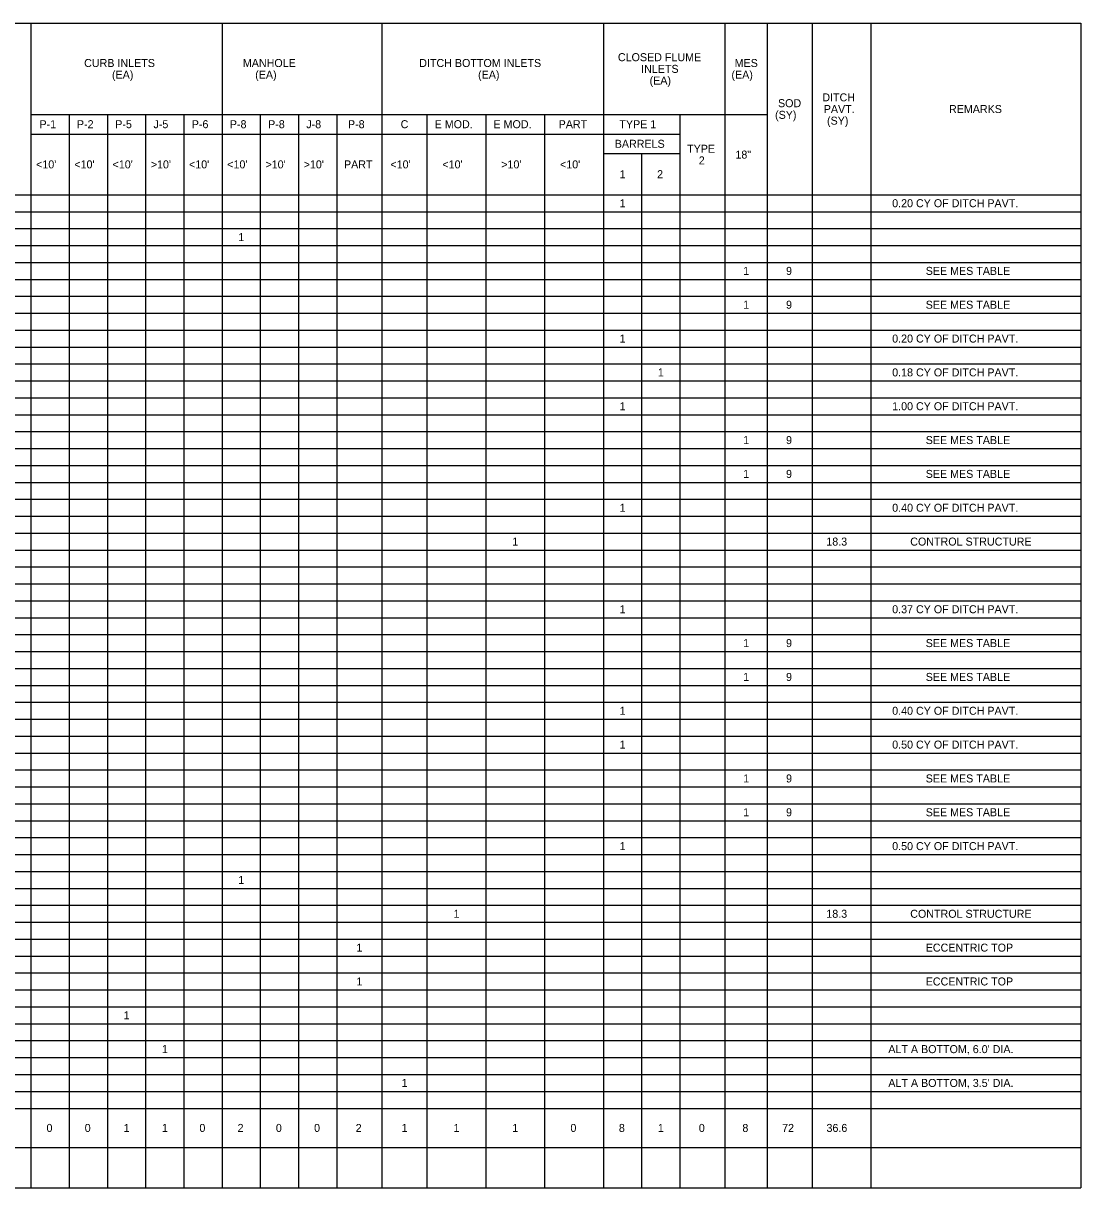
# Model space of a CAD drawing. Extents: x 0 to 765, y -1227 to 479.
# Drawn here: x 360 to 764.5, y -569 to -123.3 of the extents above; entities that cross this region are included whole.
import ezdxf

# ---------------------------------------------------------------- set-up
doc = ezdxf.new("R2010")
doc.units = 0
for name, color, linetype in [('Miscellaneous0', 7, 'Continuous'), ('PlotBorder_dp', 7, 'Continuous'), ('SheetLines_dp', 7, 'Continuous'), ('TextMinor', 7, 'Continuous')]:
    doc.layers.add(name, color=color, linetype=linetype)

msp = doc.modelspace()

# ---------------------------------------------------------------- linework, layer by layer
at = {"layer": 'PlotBorder_dp'}
for p, q in [((362.91, -123.31), (362.91, -188.93)), ((362.91, -123.31), (362.91, -568.96)), ((436.04, -123.31), (436.04, -158.18)), ((497.16, -123.31), (497.16, -568.96)), ((497.16, -123.31), (497.16, -568.96)), ((581.91, -123.31), (581.91, -568.96)), ((581.91, -123.31), (581.91, -568.96)), ((628.41, -123.31), (628.41, -568.96)), ((628.41, -123.31), (628.41, -568.96)), ((644.54, -123.31), (644.54, -568.96)), ((644.54, -123.31), (644.54, -568.96)), ((661.79, -123.31), (661.79, -568.96)), ((661.79, -123.31), (661.79, -568.96)), ((684.29, -123.31), (684.29, -188.93)), ((684.29, -123.31), (684.29, -568.96)), ((362.91, -158.18), (644.54, -158.18)), ((362.91, -158.18), (644.54, -158.18)), ((377.54, -158.18), (377.54, -188.93)), ((377.54, -158.18), (377.54, -568.96)), ((392.16, -158.18), (392.16, -188.93)), ((392.16, -158.18), (392.16, -568.96)), ((406.79, -158.18), (406.79, -568.96)), ((421.41, -158.18), (421.41, -553.58)), ((421.41, -158.18), (421.41, -568.96)), ((436.04, -158.18), (436.04, -568.96)), ((450.66, -158.18), (450.66, -568.96)), ((450.66, -158.18), (450.66, -568.96)), ((465.29, -158.18), (465.29, -568.96)), ((465.29, -158.18), (465.29, -568.96)), ((479.91, -158.18), (479.91, -568.96)), ((479.91, -158.18), (479.91, -568.96)), ((514.41, -158.18), (514.41, -568.96)), ((514.41, -158.18), (514.41, -568.96)), ((536.91, -158.18), (536.91, -568.96)), ((536.91, -158.18), (536.91, -568.96)), ((559.41, -158.18), (559.41, -568.96)), ((559.41, -158.18), (559.41, -568.96)), ((611.16, -158.18), (611.16, -568.96)), ((611.16, -158.18), (611.16, -568.96)), ((362.91, -165.68), (559.41, -165.68)), ((362.91, -165.68), (611.16, -165.68)), ((406.79, -165.68), (406.79, -553.58)), ((436.04, -165.68), (436.04, -568.96)), ((581.91, -165.68), (611.16, -165.68)), ((581.91, -173.18), (611.16, -173.18)), ((581.91, -173.18), (611.16, -173.18)), ((596.54, -173.18), (596.54, -568.96)), ((596.54, -173.18), (596.54, -568.96)), ((362.91, -422.03), (362.91, -568.96)), ((377.54, -422.03), (377.54, -553.58)), ((392.16, -422.03), (392.16, -553.58)), ((0.29, -538.58), (764.54, -538.58)), ((684.29, -538.58), (684.29, -568.96)), ((85.04, -553.58), (764.54, -553.58)), ((85.04, -553.58), (764.54, -553.58))]:
    msp.add_line(p, q, dxfattribs=at)
at = {"layer": 'SheetLines_dp'}
for p, q in [((0.29, -123.31), (764.54, -123.31)), ((764.54, -123.31), (764.54, -568.96)), ((0.29, -188.93), (764.54, -188.93)), ((40.04, -188.93), (764.54, -188.93)), ((0.29, -568.96), (764.54, -568.96))]:
    msp.add_line(p, q, dxfattribs=at)
at = {"layer": 'TextMinor'}
for p, q in [((0.29, -195.41), (764.54, -195.41)), ((173.54, -195.41), (406.79, -195.41)), ((421.41, -195.41), (764.54, -195.41)), ((0.29, -201.88), (764.54, -201.88)), ((0.29, -201.88), (764.54, -201.88)), ((0.29, -208.36), (764.54, -208.36)), ((0.29, -208.36), (764.54, -208.36)), ((0.29, -214.83), (764.54, -214.83)), ((0.29, -214.83), (764.54, -214.83)), ((0.29, -221.31), (764.54, -221.31)), ((0.29, -221.31), (764.54, -221.31)), ((0.29, -227.78), (764.54, -227.78)), ((0.29, -227.78), (764.54, -227.78)), ((0.29, -234.26), (764.54, -234.26)), ((0.29, -234.26), (764.54, -234.26)), ((0.29, -240.73), (764.54, -240.73)), ((0.29, -240.73), (764.54, -240.73)), ((0.29, -247.21), (764.54, -247.21)), ((0.29, -247.21), (764.54, -247.21)), ((0.29, -253.68), (764.54, -253.68)), ((0.29, -253.68), (764.54, -253.68)), ((0.29, -260.16), (764.54, -260.16)), ((0.29, -260.16), (764.54, -260.16)), ((0.29, -266.63), (764.54, -266.63)), ((0.29, -266.63), (764.54, -266.63)), ((0.29, -273.11), (764.54, -273.11)), ((0.29, -273.11), (764.54, -273.11)), ((0.29, -279.58), (764.54, -279.58)), ((0.29, -279.58), (764.54, -279.58)), ((0.29, -286.06), (764.54, -286.06)), ((0.29, -286.06), (764.54, -286.06)), ((0.29, -292.53), (764.54, -292.53)), ((0.29, -292.53), (764.54, -292.53)), ((0.29, -299.01), (764.54, -299.01)), ((0.29, -299.01), (764.54, -299.01)), ((0.29, -305.48), (764.54, -305.48)), ((0.29, -305.48), (764.54, -305.48)), ((0.29, -311.96), (764.54, -311.96)), ((0.29, -311.96), (764.54, -311.96)), ((0.29, -318.43), (764.54, -318.43)), ((0.29, -318.43), (764.54, -318.43)), ((0.29, -324.91), (764.54, -324.91)), ((0.29, -324.91), (764.54, -324.91)), ((0.29, -331.38), (764.54, -331.38)), ((0.29, -331.38), (764.54, -331.38)), ((0.29, -337.86), (764.54, -337.86)), ((0.29, -337.86), (764.54, -337.86)), ((0.29, -344.33), (764.54, -344.33)), ((0.29, -344.33), (764.54, -344.33)), ((0.29, -350.81), (764.54, -350.81)), ((0.29, -350.81), (764.54, -350.81)), ((0.29, -357.28), (764.54, -357.28)), ((0.29, -357.28), (764.54, -357.28)), ((0.29, -363.76), (764.54, -363.76)), ((0.29, -363.76), (764.54, -363.76)), ((0.29, -370.23), (764.54, -370.23)), ((0.29, -370.23), (764.54, -370.23)), ((0.29, -376.71), (764.54, -376.71)), ((0.29, -376.71), (764.54, -376.71)), ((0.29, -383.18), (764.54, -383.18)), ((0.29, -383.18), (764.54, -383.18)), ((0.29, -389.66), (764.54, -389.66)), ((0.29, -389.66), (764.54, -389.66)), ((0.29, -396.13), (764.54, -396.13)), ((0.29, -396.13), (764.54, -396.13)), ((0.29, -402.61), (764.54, -402.61)), ((0.29, -402.61), (764.54, -402.61)), ((0.29, -409.08), (764.54, -409.08)), ((0.29, -409.08), (764.54, -409.08)), ((0.29, -415.56), (764.54, -415.56)), ((0.29, -415.56), (764.54, -415.56)), ((0.29, -422.03), (764.54, -422.03)), ((0.29, -422.03), (764.54, -422.03)), ((0.29, -428.51), (764.54, -428.51)), ((0.29, -428.51), (764.54, -428.51)), ((0.29, -434.98), (764.54, -434.98)), ((0.29, -434.98), (764.54, -434.98)), ((0.29, -441.46), (764.54, -441.46)), ((0.29, -441.46), (764.54, -441.46)), ((0.29, -447.93), (764.54, -447.93)), ((0.29, -447.93), (764.54, -447.93)), ((0.29, -454.41), (764.54, -454.41)), ((0.29, -454.41), (764.54, -454.41)), ((0.29, -460.88), (764.54, -460.88)), ((0.29, -460.88), (764.54, -460.88)), ((0.29, -467.36), (764.54, -467.36)), ((0.29, -467.36), (764.54, -467.36)), ((0.29, -473.83), (764.54, -473.83)), ((0.29, -473.83), (764.54, -473.83)), ((0.29, -480.31), (764.54, -480.31)), ((0.29, -480.31), (764.54, -480.31)), ((0.29, -486.78), (764.54, -486.78)), ((0.29, -486.78), (764.54, -486.78)), ((0.29, -493.26), (764.54, -493.26)), ((0.29, -493.26), (764.54, -493.26)), ((0.29, -499.73), (764.54, -499.73)), ((0.29, -499.73), (764.54, -499.73)), ((0.29, -506.21), (764.54, -506.21)), ((0.29, -506.21), (764.54, -506.21)), ((0.29, -512.68), (764.54, -512.68)), ((0.29, -512.68), (764.54, -512.68)), ((0.29, -519.16), (764.54, -519.16)), ((0.29, -519.16), (764.54, -519.16)), ((0.29, -525.63), (764.54, -525.63)), ((0.29, -525.63), (764.54, -525.63)), ((0.29, -532.11), (764.54, -532.11)), ((0.29, -532.11), (764.54, -532.11)), ((0.29, -538.58), (764.54, -538.58))]:
    msp.add_line(p, q, dxfattribs=at)

# ---------------------------------------------------------------- texts
at = {"layer": 'Miscellaneous0'}
for s, height, p in [('CURB INLETS', 3.0625, (383.28, -140.04)), ('MANHOLE ', 3.062, (444, -140.04)), ('DITCH BOTTOM INLETS', 3.0625, (511.48, -140.04)), ('CLOSED FLUME', 3.0625, (587.48, -137.81)), ('MES', 3.062, (632.14, -140.04)), ('(EA)', 3.062, (393.93, -144.51)), ('(EA)', 3.062, (448.72, -144.51)), ('(EA)', 3.062, (533.99, -144.51)), ('INLETS', 3.062, (596.38, -142.28)), ('(EA)', 3.062, (630.93, -144.51)), ('(EA)', 3.062, (599.61, -146.74)), ('DITCH', 3.062, (665.69, -153.19)), ('SOD', 3.062, (648.73, -155.42)), ('PAVT.', 3.062, (666.24, -157.65)), ('REMARKS', 3.062, (714.15, -157.65)), ('P-1', 3.062, (366.18, -163.46)), ('P-2', 3.062, (380.51, -163.46)), ('P-5', 3.062, (395.18, -163.46)), ('J-5', 3.062, (409.8, -163.46)), ('P-6', 3.062, (424.45, -163.46)), ('P-8', 3.062, (439.02, -163.46)), ('P-8', 3.062, (453.65, -163.46)), ('J-8', 3.062, (468.27, -163.46)), ('P-8', 3.062, (484.21, -163.46)), ('C', 3.06, (504.35, -163.46)), ('E MOD.', 3.062, (517.38, -163.46)), ('E MOD.', 3.062, (539.88, -163.46)), ('PART', 3.062, (564.81, -163.46)), ('TYPE 1', 3.062, (588.05, -163.46)), ('(SY)', 3.062, (647.61, -159.88)), ('(SY)', 3.062, (667.49, -162.11)), ('BARRELS', 3.062, (586.27, -170.96)), ('TYPE', 3.062, (613.96, -172.86)), ('18"', 3.062, (632.44, -175.09)), ("<10'", 3.062, (364.9, -178.84)), ("<10'", 3.062, (379.52, -178.84)), ("<10'", 3.062, (394.15, -178.84)), (">10'", 3.062, (408.77, -178.84)), ("<10'", 3.062, (423.4, -178.84)), ("<10'", 3.062, (438.02, -178.84)), (">10'", 3.062, (452.65, -178.84)), (">10'", 3.062, (467.27, -178.84)), ('PART', 3.062, (482.69, -178.84)), ("<10'", 3.062, (500.46, -178.84)), ("<10'", 3.062, (520.34, -178.84)), (">10'", 3.062, (542.84, -178.84)), ("<10'", 3.062, (565.34, -178.84)), ('2', 3.06, (618.42, -177.32)), ('1', 3.06, (588.15, -182.59)), ('2', 3.06, (602.48, -182.59)), ('1', 3.06, (588.15, -193.7)), ('0.20 CY OF DITCH PAVT.', 3.0625, (692.42, -193.7)), ('1', 3.06, (442.27, -206.65)), ('1', 3.06, (635.4, -219.6)), ('9', 3.06, (651.81, -219.6)), ('SEE MES TABLE', 3.0625, (705.24, -219.6)), ('1', 3.06, (635.4, -232.55)), ('9', 3.06, (651.81, -232.55)), ('SEE MES TABLE', 3.0625, (705.24, -232.55)), ('1', 3.06, (588.15, -245.5)), ('0.20 CY OF DITCH PAVT.', 3.0625, (692.42, -245.5)), ('1', 3.06, (602.77, -258.45)), ('0.18 CY OF DITCH PAVT.', 3.0625, (692.42, -258.45)), ('1', 3.06, (588.15, -271.4)), ('1.00 CY OF DITCH PAVT.', 3.0625, (692.42, -271.4)), ('1', 3.06, (635.4, -284.35)), ('9', 3.06, (651.81, -284.35)), ('SEE MES TABLE', 3.0625, (705.24, -284.35)), ('1', 3.06, (635.4, -297.3)), ('9', 3.06, (651.81, -297.3)), ('SEE MES TABLE', 3.0625, (705.24, -297.3)), ('1', 3.06, (588.15, -310.25)), ('0.40 CY OF DITCH PAVT.', 3.0625, (692.42, -310.25)), ('1', 3.06, (547.09, -323.2)), ('18.3', 3.062, (667.22, -323.2)), ('CONTROL STRUCTURE', 3.0625, (699.32, -323.2)), ('1', 3.06, (588.15, -349.1)), ('0.37 CY OF DITCH PAVT.', 3.0625, (692.42, -349.1)), ('1', 3.06, (635.4, -362.05)), ('9', 3.06, (651.81, -362.05)), ('SEE MES TABLE', 3.0625, (705.24, -362.05)), ('1', 3.06, (635.4, -375)), ('9', 3.06, (651.81, -375)), ('SEE MES TABLE', 3.0625, (705.24, -375)), ('1', 3.06, (588.15, -387.95)), ('0.40 CY OF DITCH PAVT.', 3.0625, (692.42, -387.95)), ('1', 3.06, (588.15, -400.9)), ('0.50 CY OF DITCH PAVT.', 3.0625, (692.42, -400.9)), ('1', 3.06, (635.4, -413.85)), ('9', 3.06, (651.81, -413.85)), ('SEE MES TABLE', 3.0625, (705.24, -413.85)), ('1', 3.06, (635.4, -426.8)), ('9', 3.06, (651.81, -426.8)), ('SEE MES TABLE', 3.0625, (705.24, -426.8)), ('1', 3.06, (588.15, -439.75)), ('0.50 CY OF DITCH PAVT.', 3.0625, (692.42, -439.75)), ('1', 3.06, (442.27, -452.7)), ('1', 3.06, (524.59, -465.65)), ('18.3', 3.062, (667.22, -465.65)), ('CONTROL STRUCTURE', 3.0625, (699.32, -465.65)), ('1', 3.06, (487.46, -478.6)), ('ECCENTRIC TOP', 3.0625, (705.24, -478.6)), ('1', 3.06, (487.46, -491.55)), ('ECCENTRIC TOP', 3.0625, (705.24, -491.55)), ('1', 3.06, (398.4, -504.5)), ('1', 3.06, (413.02, -517.45)), ("ALT A BOTTOM, 6.0' DIA.", 3.0625, (690.94, -517.45)), ('1', 3.06, (504.71, -530.4)), ("ALT A BOTTOM, 3.5' DIA.", 3.0625, (690.94, -530.4)), ('0', 3.06, (368.88, -547.61)), ('0', 3.06, (383.5, -547.61)), ('1', 3.06, (398.4, -547.61)), ('1', 3.06, (413.02, -547.61)), ('0', 3.06, (427.38, -547.61)), ('2', 3.06, (441.98, -547.61)), ('0', 3.06, (456.63, -547.61)), ('0', 3.06, (471.25, -547.61)), ('2', 3.06, (487.17, -547.61)), ('1', 3.06, (504.71, -547.61)), ('1', 3.06, (524.59, -547.61)), ('1', 3.06, (547.09, -547.61)), ('0', 3.06, (569.32, -547.61)), ('8', 3.06, (587.86, -547.61)), ('1', 3.06, (602.77, -547.61)), ('0', 3.06, (618.44, -547.61)), ('8', 3.06, (635.11, -547.61)), ('72', 3.062, (650.31, -547.61)), ('36.6', 3.062, (667.28, -547.61))]:
    msp.add_text(s, height=height, dxfattribs=at).set_placement(p)

doc.saveas('drawing.dxf')
